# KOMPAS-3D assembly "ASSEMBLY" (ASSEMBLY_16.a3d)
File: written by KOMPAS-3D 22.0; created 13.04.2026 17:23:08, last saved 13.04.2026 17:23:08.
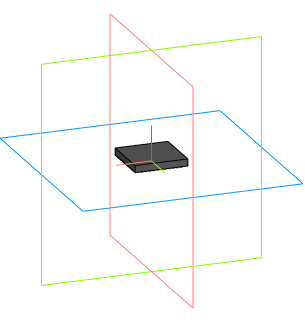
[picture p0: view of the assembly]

Document properties: Автор: Andrey; Полное имя файла: C:\Users\User1\Documents\ASSEMBLY_16.a3d

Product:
- Component [detail]: Body  | qty 1  | source file: Body_17.m3d
- Component [detail]: Pins  | qty 1  | source file: Pins_18.m3d
- Part/product: ASSEMBLY

Referenced files in C:\Users\User1\Documents\: Body_17.m3d, Pins_18.m3d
